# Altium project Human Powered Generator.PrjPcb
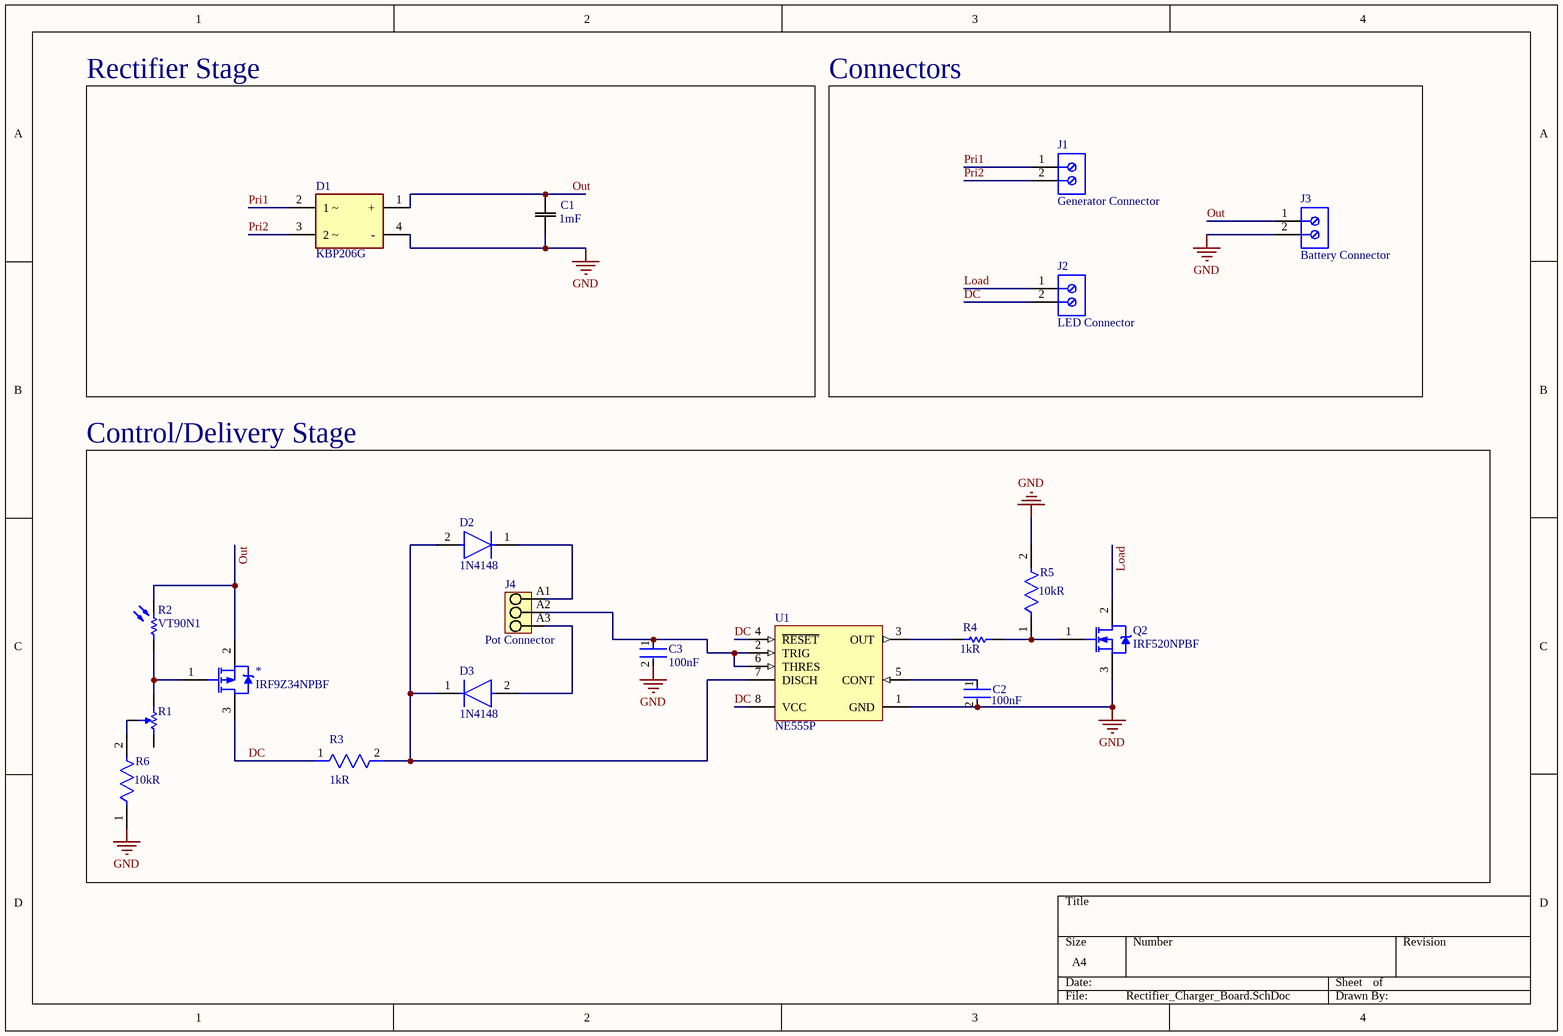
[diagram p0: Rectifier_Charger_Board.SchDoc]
1 sheet, 19 parts. Net scope: global (net labels, ports and power ports of the same name join across sheets).
Board file: MainBoard.PcbDoc

## Sheet Rectifier_Charger_Board.SchDoc
size A4; SheetNumber: 1; SheetTotal: 1

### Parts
*  IRF9Z34NPBF  [IRF9Z34NPBF-Footprint-1]
C1  Capacitance: 1mF  [16YXJ1000MT810X16-Footprint-1]  (hidden comment: 16YXJ1000MT810X16)
C2  Capacitance: 100nF  [FP-C322C104K5R5TA-MFG]  (hidden comment: C322C104K5R5TA)
C3  Capacitance: 100nF  [FP-C322C104K5R5TA-MFG]  (hidden comment: C322C104K5R5TA)
D1  KBP206G  [FP-KBP-MFG]
D2  1N4148  [FP-017AG-MFG]
D3  1N4148  [FP-017AG-MFG]
J1  Generator Connector  [691137710002]
J2  LED Connector  [691137710002]
J3  Battery Connector  [691137710002]
J4  Pot Connector  [LSF_SMT_5_00_180_03]
Q2  IRF520NPBF  [INTR-TO-220AB-3]
R1  3386P-1-104LF  [BOUR-3386P]  (value not drawn)
R2  VT90N1  [EXCE-VT90N1]
R3  Resistance: 1kR  [New footprint 1]  (hidden comment: CFR-25JB-52-1K)
R4  Resistance: 1kR  [RESA60-630X240]  (hidden comment: MFR-25FBF52-1K)
R5  value 10kR  [FP-CF18-MFG]  (hidden comment: CF18JT10K0)
R6  value 10kR  [FP-CF18-MFG]  (hidden comment: CF18JT10K0)
U1  NE555P  [P0008A]

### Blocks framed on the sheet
Rectifier Stage: C1 D1
Connectors: J1-J3
Control/Delivery Stage: * C2 C3 D2 D3 J4 Q2 R1-R6 U1

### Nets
GND: C1.1 C2.2 C3.2 D1.4(-) J3.2 Q2.3(S) R5.2 R6.1 U1.1(GND)
DC: *.3(S) J2.2 R3.1 U1.4(~{RESET}) U1.8(VCC)
Load: J2.1 Q2.2(D)
Out: *.2(D) C1.2 D1.1(+) J3.1 R2.2
Pri1: D1.2(1_~) J1.1
Pri2: D1.3(2_~) J1.2
Net*_1: *.1(G) R1.1 R2.1
NetC2_1: C2.1 U1.5(CONT)
NetC3_1: C3.1 J4.A2 U1.2(TRIG) U1.6(THRES)
NetD2_1: D2.1(C) J4.A1
NetD2_2: D2.2(A) D3.1(C) R3.2 U1.7(DISCH)
NetD3_2: D3.2(A) J4.A3
NetQ2_1: Q2.1(G) R4.2 R5.1
NetR1_2: R1.2 R6.2
NetR4_1: R4.1 U1.3(OUT)

Not connected (* = marked no-connect by the designer): R1 3

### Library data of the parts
* = CMP-013-00034-5: Mosfet, Power; P-ch; Vdss -55V; Rds(on) 0.1 Ohm; Id -19A; TO-220AB; Pd 68W; Vgs +/-20V
C1 = CMP-001-00083-1: Cap Aluminum Lytic 1000uF 16V 20% (10 X 16mm) Radial 5mm 1210mA 10000h 105°C Ammo; Ripple Current: 1.21A; Impedance: 62mR
C2 C3 = CMP-03020-034661-1: CAP CER 0.1UF 50V X7R RADIAL; Dielectric Material: Ceramic; Dissipation Factor: 2.5%; Lead Length: 7mm; Tolerance: 10%; Lead Diameter: 0.51mm; Lead/Base Style: Formed Leads
D1 = CMP-12791-000035-1: BRIDGE RECT 1PHASE 600V 2A KBP; Manufacturer: Diodes Inc.; Capacitance: 25pF; Max Junction Temp: +150°C; Value: 25pF; Max Surge Forward Current: 65A; Peak Reverse Current: 5uA; Standoff Height: 1.8mm
D2 D3 = CMP-07163-000046-1: DIODE GEN PURP 100V 200MA DO35; Forward Voltage: 1V; Max Power Dissipation: 500mW; Max Reverse Current: 5uA; Forward Current: 300mA; Current: 4A; Reverse Recovery Time: 4ns; Element Configuration: Single; Outside Diameter: 1.85mm; Capacitance: 4pF; Polarity: Standard; Max Forward Surge Current (Ifsm): 1A
J1-J3 = CMP-1502-03324-1: Series 1377 - 5.00 mm Horizontal Entry with Pressure Clamp WR-TBL, 2 pin; Manufacturer: Wurth Elektronik; Pin Number: 2; Pitch: 5.00mm
J4 = CMP-1559-02314-1: OMNIMATE Signal - series LSF; PartNumber: 1825970000; Manufacturer: Weidmueller; UL_94_flammability_rating: V-0; Rated_current_use_group_B_UL_1059: 12 A; No_of_poles: 3; Insulating_material: LCP GF; Solid_max_H05_07_V_U: 1,5 mm²; Wire_cross_section_AWG_min_UL_1059: AWG 24; Mounting_onto_the_PCB: Reflow solder connection; Short_text_for_material: LSF-SMT 5.00/03/180 3.5SN BK TU; Wire_cross_section_AWG_max_UL_1059: AWG 16; Solid_min_H05_07_V_U: 0,2 mm²; Pitch_mm: 5 mm; Rated_voltage_use_group_B_UL_1059: 300 V; Rated_voltage_for_surge_voltage_class_pollution_degree_II_2: 500 V; Rated_current_min_no_of_poles_TU_20_deg_C: 19 A; Contact_material: Cu-Leg; Side_termination_characteristic: closed side; Contact_surface: tinned; Pitch_inch: 0,197 inch; Solder_pin_length_mm: 3,5 mm
Q2 = CMP-2100-03647-1: HEXFET(R) Power MOSFET, 100 V, 9.7 A, 0.2 Ohm, -55 to 175 degC, 3-Pin FM (TO-220AB), RoHS, Tube; Manufacturer: International Rectifier; Element Configuration: Single; Rds On Max: 200mOhm; Drain to Source Voltage (Vdss): 100V; Number of Elements: 1; Continuous Drain Current (ID): 9.7A; Input Capacitance: 330pF; Gate to Source Voltage (Vgs): 20V; Power Dissipation: 48W; Rise Time: 23ns; Turn-Off Delay Time: 32ns; Turn-On Delay Time: 4.5ns
R1 = CMP-2000-05592-1: Square Trimpot(R) Trimming Potentiometer, 100 KOhm, +/- 10%, 0.5 W, -55 to 125 degC, 3-Pin THD, RoHS, Tube; Manufacturer Series: 3386; Manufacturer: Bourns; Resistive Element Material: Cermet; Shaft Diameter: 3.15mm; Number of Turns: 1; Product Height: 4.83mm; Temperature Coefficient: 100ppm/C; Product Depth: 9.53mm; Rated Temperature (Cel): 85; Actuator Orientation: Vertical; Resistance (ohm): 100000; Power Rating: 1/2W; Tolerance (%): 10; Rated Power Dissipation (P) (W): 0.5; Resistance Law: Linear; Actuator Type: Screw
R2 = CMP-2000-07406-1: Photoconductive Resistor, 200 kOhm, 100 V, 80 mW, -40 to 75 degC, 2-Pin THD, RoHS; Manufacturer: Excelitas Technology; SVHC: Cadmiumchloride(15-Jun-2015); Power Rating: 80mW; Resistance @ Lux: 12kohm; Voltage Rating: 100V
R3 = CMP-009-00177-2: Res Carbon Film 1K Ohm 5% 1/4W -350ppm/°C to 350ppm/°C Conformal AXL Thru-Hole Bulk; Max Power Dissipation: 250mW
R4 = CMP-1659-00075-1: Axial Resistor, 1 KOhm, +/- 1%, 250 mW, -55 to 155 degC, 2-Pin THD, RoHS, Bulk; Voltage Rating: 250 V; Power Rating: 250 mW
R5 R6 = CMP-26528-000002-1: RES 10K OHM 1/8W 5% CF AXIAL; Manufacturer: Stackpole Electronics; Power Rating: 0.125W; Temperature Coefficient: 0-500ppm/°C; Resistance: 10kΩ; Voltage Rating: 250V
U1 = CMP-2000-04954-1: Precision Timer, 4.5 to 16 V, 0 to 70 degC, 8-Pin DIP, Pb-Free, Tube; Manufacturer: TexasInstruments; Maximum High Level Output Current: -200mA; Number of Internal Timers: 1; Operating Supply Voltage: 5; Maximum Low Level Output Current: 200mA; Rad Hard: No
